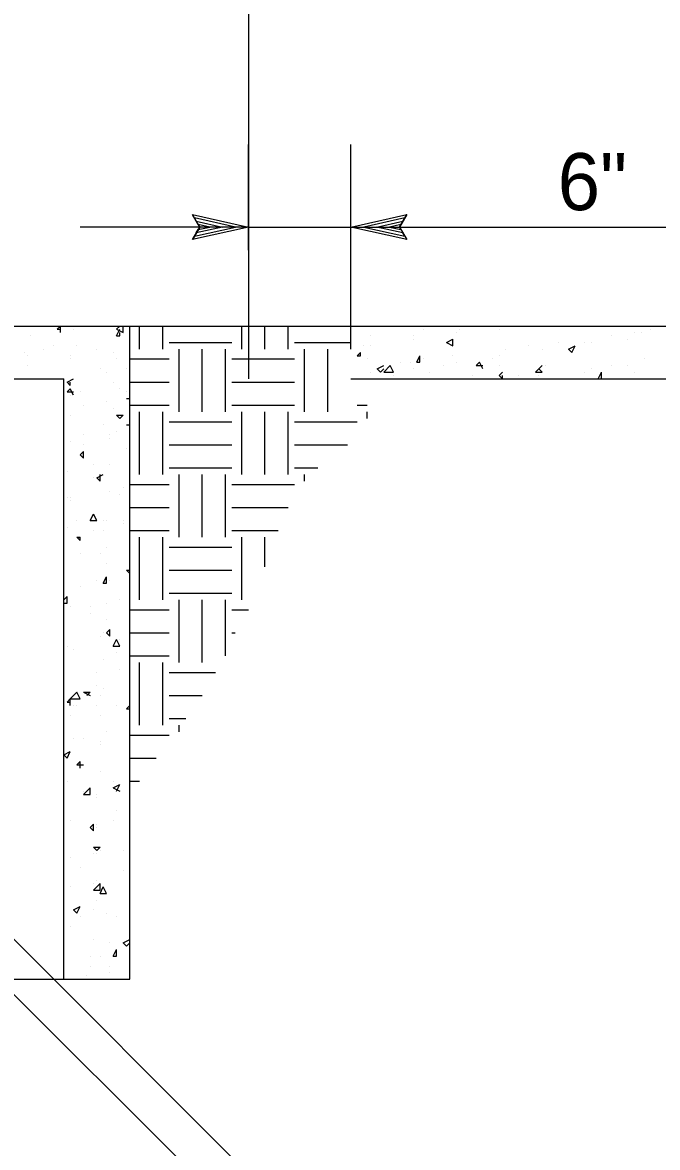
# Model space of a CAD drawing. Extents: x -119017 to -116080, y -104449 to -102845.
# Drawn here: x -116465.6 to -116398.8, y -103374.5 to -103256.1 of the extents above; entities that cross this region are included whole.
import ezdxf

# ---------------------------------------------------------------- set-up
doc = ezdxf.new("R2010")
doc.units = 0
for name, color, linetype in [('G-MARK', 7, 'Continuous'), ('G-TEXT', 7, 'Continuous'), ('Misc CnstDet(22)', 7, 'Continuous')]:
    doc.layers.add(name, color=color, linetype=linetype)

msp = doc.modelspace()

# ---------------------------------------------------------------- linework, layer by layer
at = {"layer": 'G-MARK'}
for p, q in [((-116441.82, -103280.07), (-116441.82, -103268.96)), ((-116431.07, -103290.48), (-116431.07, -103268.96)), ((-116441.82, -103277.64), (-116459.53, -103277.64)), ((-116441.82, -103277.64), (-116431.07, -103277.64)), ((-116431.07, -103277.64), (-116392.89, -103277.64))]:
    msp.add_line(p, q, dxfattribs=at)
at = {"layer": 'G-TEXT'}
for points in [[(-116447.73, -103276.32), (-116441.82, -103277.64), (-116447.73, -103278.95), (-116447.52, -103278.6), (-116443.19, -103277.64), (-116447.52, -103276.67), (-116447.31, -103277.02), (-116444.54, -103277.64), (-116447.31, -103278.25), (-116447.1, -103277.9), (-116445.9, -103277.64), (-116447.1, -103277.37), (-116446.94, -103277.64), (-116447.73, -103278.95), (-116446.94, -103277.64)], [(-116425.16, -103278.96), (-116431.07, -103277.64), (-116425.16, -103276.33), (-116425.37, -103276.68), (-116429.7, -103277.64), (-116425.37, -103278.61), (-116425.58, -103278.26), (-116428.35, -103277.64), (-116425.58, -103277.03), (-116425.79, -103277.38), (-116426.99, -103277.64), (-116425.79, -103277.91), (-116425.95, -103277.64), (-116425.16, -103276.33), (-116425.95, -103277.64)]]:
    msp.add_lwpolyline(points, close=True, dxfattribs=at)
at = {"layer": 'Misc CnstDet(22)'}
for p, q in [((-116441.82, -103024.96), (-116441.82, -103293.61)), ((-116431.07, -103277.64), (-116431.07, -103277.64)), ((-116441.82, -103283.19), (-116441.82, -103283.19)), ((-116614.33, -103288.05), (-116319.3, -103288.05)), ((-116462.3, -103288.05), (-116462.3, -103288.05)), ((-116461.96, -103288.4), (-116461.61, -103288.05)), ((-116461.96, -103288.4), (-116461.61, -103288.4)), ((-116461.61, -103288.75), (-116461.61, -103288.05)), ((-116460.22, -103288.4), (-116460.22, -103288.4)), ((-116455.71, -103288.4), (-116455.36, -103288.05)), ((-116455.71, -103288.4), (-116455.01, -103288.75)), ((-116455.71, -103289.09), (-116455.36, -103288.4)), ((-116455.36, -103289.09), (-116455.36, -103288.75)), ((-116455.01, -103288.75), (-116455.01, -103288.05)), ((-116454.32, -103356.78), (-116454.32, -103288.05)), ((-116453.28, -103290.48), (-116453.28, -103288.05)), ((-116450.85, -103290.48), (-116450.85, -103288.05)), ((-116442.52, -103290.48), (-116442.52, -103288.05)), ((-116440.09, -103290.48), (-116440.09, -103288.05)), ((-116437.66, -103290.48), (-116437.66, -103288.05)), ((-116423.43, -103288.4), (-116423.43, -103288.4)), ((-116421.35, -103288.05), (-116421.35, -103288.05)), ((-116419.96, -103288.75), (-116419.96, -103288.75)), ((-116419.61, -103288.4), (-116419.61, -103288.4)), ((-116415.45, -103288.4), (-116415.45, -103288.4)), ((-116401.22, -103288.75), (-116401.22, -103288.75)), ((-116400.52, -103288.75), (-116400.52, -103288.75)), ((-116399.48, -103288.4), (-116399.48, -103288.4)), ((-116464.73, -103289.09), (-116464.73, -103289.09)), ((-116455.71, -103289.09), (-116455.36, -103289.09)), ((-116450.16, -103289.79), (-116443.56, -103289.79)), ((-116436.97, -103289.79), (-116431.07, -103289.79)), ((-116428.98, -103289.09), (-116428.98, -103289.09)), ((-116424.47, -103289.09), (-116424.47, -103289.09)), ((-116424.47, -103289.44), (-116424.47, -103289.44)), ((-116421, -103289.79), (-116420.31, -103289.44)), ((-116421, -103289.79), (-116420.31, -103290.13)), ((-116420.31, -103290.13), (-116420.31, -103289.44)), ((-116409.2, -103289.79), (-116409.2, -103289.79)), ((-116406.42, -103289.79), (-116406.42, -103289.79)), ((-116405.73, -103289.79), (-116405.73, -103289.79)), ((-116403.64, -103289.09), (-116403.64, -103289.09)), ((-116401.91, -103289.44), (-116401.91, -103289.44)), ((-116465.43, -103290.83), (-116465.43, -103290.83)), ((-116463.34, -103290.48), (-116463.34, -103290.48)), ((-116462.3, -103290.13), (-116462.3, -103290.13)), ((-116459.87, -103290.13), (-116459.87, -103290.13)), ((-116457.79, -103290.48), (-116457.79, -103290.48)), ((-116456.06, -103290.83), (-116456.06, -103290.83)), ((-116449.11, -103297.08), (-116449.11, -103290.48)), ((-116446.68, -103297.08), (-116446.68, -103290.48)), ((-116444.25, -103297.08), (-116444.25, -103290.48)), ((-116435.92, -103297.08), (-116435.92, -103290.48)), ((-116433.49, -103297.08), (-116433.49, -103290.48)), ((-116430.37, -103291.18), (-116430.02, -103290.83)), ((-116430.02, -103291.18), (-116430.02, -103290.83)), ((-116429.68, -103290.13), (-116429.68, -103290.13)), ((-116428.98, -103290.13), (-116428.98, -103290.13)), ((-116414.75, -103290.48), (-116414.75, -103290.48)), ((-116412.32, -103290.13), (-116412.32, -103290.13)), ((-116410.93, -103290.48), (-116410.93, -103290.48)), ((-116410.93, -103290.48), (-116410.93, -103290.48)), ((-116408.16, -103290.48), (-116407.46, -103290.13)), ((-116408.16, -103290.48), (-116407.81, -103290.83)), ((-116407.81, -103290.83), (-116407.46, -103290.13)), ((-116465.08, -103291.18), (-116465.08, -103291.18)), ((-116465.08, -103292.22), (-116465.08, -103292.22)), ((-116460.57, -103291.18), (-116460.57, -103291.18)), ((-116460.57, -103291.52), (-116460.57, -103291.52)), ((-116455.71, -103291.52), (-116455.71, -103291.52)), ((-116454.32, -103291.52), (-116450.16, -103291.52)), ((-116443.56, -103291.52), (-116436.97, -103291.52)), ((-116430.37, -103291.18), (-116430.02, -103291.18)), ((-116429.33, -103291.52), (-116429.33, -103291.52)), ((-116428.29, -103292.56), (-116427.59, -103292.22)), ((-116427.59, -103292.91), (-116426.9, -103292.22)), ((-116426.55, -103292.91), (-116426.9, -103292.22)), ((-116425.86, -103291.87), (-116425.86, -103291.87)), ((-116424.82, -103291.87), (-116424.82, -103291.87)), ((-116424.12, -103291.87), (-116423.78, -103291.18)), ((-116424.12, -103291.87), (-116423.78, -103291.87)), ((-116423.78, -103291.87), (-116423.78, -103291.18)), ((-116423.43, -103291.52), (-116423.43, -103291.52)), ((-116421.35, -103292.22), (-116421.35, -103292.22)), ((-116420.31, -103291.18), (-116420.31, -103291.18)), ((-116419.96, -103291.87), (-116419.96, -103291.87)), ((-116419.96, -103291.87), (-116419.96, -103291.87)), ((-116417.88, -103292.22), (-116417.53, -103291.87)), ((-116417.88, -103292.22), (-116417.18, -103292.22)), ((-116417.18, -103292.56), (-116417.53, -103291.87)), ((-116416.14, -103291.52), (-116416.14, -103291.52)), ((-116415.45, -103291.18), (-116415.45, -103291.18)), ((-116415.45, -103292.22), (-116415.45, -103292.22)), ((-116411.63, -103292.91), (-116410.93, -103292.22)), ((-116410.59, -103292.22), (-116410.59, -103292.22)), ((-116403.64, -103292.22), (-116403.64, -103292.22)), ((-116401.91, -103292.22), (-116401.91, -103292.22)), ((-116400.17, -103291.52), (-116400.17, -103291.52)), ((-116457.44, -103292.56), (-116457.44, -103292.56)), ((-116456.75, -103292.91), (-116456.75, -103292.91)), ((-116454.67, -103292.56), (-116454.67, -103292.56)), ((-116428.98, -103292.91), (-116428.98, -103292.91)), ((-116428.29, -103292.56), (-116427.94, -103292.91)), ((-116427.94, -103292.91), (-116427.59, -103292.56)), ((-116427.59, -103292.56), (-116427.59, -103292.56)), ((-116427.59, -103292.91), (-116426.55, -103292.91)), ((-116426.55, -103293.26), (-116426.55, -103293.26)), ((-116424.47, -103292.56), (-116424.47, -103292.56)), ((-116422.73, -103292.91), (-116422.73, -103292.91)), ((-116418.22, -103293.26), (-116418.22, -103293.26)), ((-116415.45, -103293.26), (-116415.1, -103292.91)), ((-116415.45, -103293.26), (-116415.1, -103293.61)), ((-116415.1, -103293.61), (-116415.1, -103293.26)), ((-116413.36, -103293.26), (-116413.36, -103293.26)), ((-116411.63, -103292.91), (-116410.93, -103292.91)), ((-116410.93, -103292.91), (-116411.28, -103292.56)), ((-116411.28, -103293.26), (-116411.28, -103293.26)), ((-116406.42, -103292.91), (-116406.42, -103292.91)), ((-116405.73, -103292.56), (-116405.73, -103292.56)), ((-116405.73, -103292.56), (-116405.73, -103292.56)), ((-116405.03, -103293.61), (-116404.69, -103292.91)), ((-116404.69, -103293.61), (-116404.69, -103292.91)), ((-116401.22, -103292.91), (-116401.22, -103292.91)), ((-116468.2, -103293.61), (-116461.26, -103293.61)), ((-116462.65, -103293.61), (-116462.65, -103293.61)), ((-116462.3, -103293.61), (-116462.3, -103293.61)), ((-116461.26, -103356.78), (-116461.26, -103293.61)), ((-116460.91, -103293.95), (-116460.22, -103293.61)), ((-116460.91, -103293.95), (-116460.57, -103294.3)), ((-116460.91, -103294.99), (-116460.57, -103294.65)), ((-116460.57, -103294.3), (-116460.57, -103293.95)), ((-116460.57, -103294.3), (-116460.57, -103294.3)), ((-116460.22, -103295.34), (-116460.57, -103294.65)), ((-116456.06, -103293.95), (-116456.06, -103293.95)), ((-116455.36, -103294.65), (-116455.36, -103294.65)), ((-116454.32, -103293.95), (-116450.16, -103293.95)), ((-116443.56, -103293.95), (-116436.97, -103293.95)), ((-116431.07, -103293.61), (-116337.35, -103293.61)), ((-116431.07, -103293.61), (-116431.07, -103293.61)), ((-116414.75, -103293.61), (-116414.75, -103293.61)), ((-116410.93, -103293.61), (-116410.93, -103293.61)), ((-116408.85, -103293.61), (-116408.85, -103293.61)), ((-116405.03, -103293.61), (-116404.69, -103293.61)), ((-116460.91, -103294.99), (-116460.22, -103294.99)), ((-116460.57, -103295.34), (-116460.57, -103295.34)), ((-116459.53, -103294.99), (-116459.53, -103294.99)), ((-116454.67, -103294.99), (-116454.67, -103294.99)), ((-116454.67, -103295.69), (-116454.32, -103295.69)), ((-116454.67, -103295.69), (-116454.32, -103295.69)), ((-116459.18, -103296.38), (-116459.18, -103296.38)), ((-116456.75, -103296.03), (-116456.75, -103296.03)), ((-116456.06, -103296.73), (-116456.06, -103296.73)), ((-116454.32, -103296.38), (-116450.16, -103296.38)), ((-116443.56, -103296.38), (-116436.97, -103296.38)), ((-116430.37, -103296.38), (-116429.33, -103296.38)), ((-116460.57, -103297.42), (-116460.57, -103297.42)), ((-116455.71, -103297.42), (-116455.36, -103297.77)), ((-116455.71, -103297.42), (-116455.01, -103297.42)), ((-116455.36, -103297.77), (-116455.01, -103297.42)), ((-116453.28, -103303.67), (-116453.28, -103297.08)), ((-116450.85, -103303.67), (-116450.85, -103297.08)), ((-116450.16, -103298.12), (-116443.56, -103298.12)), ((-116442.52, -103303.67), (-116442.52, -103297.08)), ((-116440.09, -103303.67), (-116440.09, -103297.08)), ((-116437.66, -103303.67), (-116437.66, -103297.08)), ((-116436.97, -103298.12), (-116430.37, -103298.12)), ((-116429.33, -103297.77), (-116429.33, -103297.08)), ((-116457.1, -103298.46), (-116457.1, -103298.46)), ((-116455.71, -103299.16), (-116455.71, -103299.16)), ((-116454.67, -103298.46), (-116454.32, -103298.46)), ((-116454.67, -103298.46), (-116454.32, -103298.46)), ((-116461.26, -103299.51), (-116461.26, -103299.51)), ((-116460.57, -103300.2), (-116460.57, -103300.2)), ((-116459.18, -103299.51), (-116459.18, -103299.51)), ((-116459.18, -103300.55), (-116459.18, -103300.55)), ((-116456.4, -103299.51), (-116456.4, -103299.51)), ((-116456.4, -103299.85), (-116456.4, -103299.85)), ((-116450.16, -103300.55), (-116443.56, -103300.55)), ((-116436.97, -103300.55), (-116431.41, -103300.55)), ((-116459.53, -103301.59), (-116459.18, -103301.24)), ((-116459.53, -103301.59), (-116459.18, -103301.94)), ((-116459.18, -103301.94), (-116459.18, -103301.24)), ((-116454.67, -103300.89), (-116454.67, -103300.89)), ((-116458.14, -103302.63), (-116458.14, -103302.63)), ((-116456.4, -103302.63), (-116456.4, -103302.63)), ((-116460.91, -103303.32), (-116460.91, -103303.32)), ((-116458.14, -103304.02), (-116458.14, -103304.02)), ((-116457.79, -103304.02), (-116457.1, -103303.67)), ((-116457.79, -103304.02), (-116457.44, -103304.37)), ((-116457.44, -103303.67), (-116457.44, -103303.67)), ((-116457.44, -103304.37), (-116457.44, -103303.67)), ((-116450.16, -103302.98), (-116443.56, -103302.98)), ((-116449.11, -103310.27), (-116449.11, -103303.67)), ((-116446.68, -103310.27), (-116446.68, -103303.67)), ((-116444.25, -103310.27), (-116444.25, -103303.67)), ((-116436.97, -103302.98), (-116434.54, -103302.98)), ((-116435.92, -103304.37), (-116435.92, -103303.67)), ((-116455.01, -103305.06), (-116455.01, -103305.06)), ((-116454.32, -103304.71), (-116450.16, -103304.71)), ((-116443.56, -103304.71), (-116436.97, -103304.71)), ((-116460.91, -103306.1), (-116460.91, -103306.1)), ((-116460.57, -103306.1), (-116460.57, -103306.1)), ((-116460.57, -103306.45), (-116460.57, -103306.45)), ((-116456.4, -103305.41), (-116456.4, -103305.41)), ((-116455.36, -103305.75), (-116455.36, -103305.75)), ((-116454.32, -103307.14), (-116450.16, -103307.14)), ((-116443.56, -103307.14), (-116437.66, -103307.14)), ((-116459.87, -103308.53), (-116459.87, -103308.53)), ((-116458.49, -103308.53), (-116458.14, -103307.84)), ((-116458.49, -103308.53), (-116457.79, -103308.53)), ((-116457.79, -103308.53), (-116458.14, -103307.84)), ((-116457.1, -103308.53), (-116457.1, -103308.53)), ((-116456.75, -103308.53), (-116456.75, -103308.53)), ((-116455.01, -103308.53), (-116455.01, -103308.53)), ((-116455.01, -103308.88), (-116455.01, -103308.88)), ((-116460.91, -103309.22), (-116460.91, -103309.22)), ((-116458.14, -103309.57), (-116458.14, -103309.57)), ((-116457.1, -103309.57), (-116457.1, -103309.57)), ((-116454.32, -103309.57), (-116450.16, -103309.57)), ((-116443.56, -103309.57), (-116438.7, -103309.57)), ((-116459.87, -103310.27), (-116459.53, -103310.61)), ((-116459.87, -103310.27), (-116459.53, -103310.27)), ((-116459.53, -103310.61), (-116459.53, -103310.27)), ((-116453.28, -103316.86), (-116453.28, -103310.27)), ((-116450.85, -103316.86), (-116450.85, -103310.27)), ((-116442.52, -103316.86), (-116442.52, -103310.27)), ((-116440.09, -103313.39), (-116440.09, -103310.27)), ((-116461.26, -103312), (-116461.26, -103312)), ((-116459.53, -103312), (-116459.53, -103312)), ((-116457.44, -103312), (-116457.44, -103312)), ((-116456.75, -103311.31), (-116456.75, -103311.31)), ((-116450.16, -103311.31), (-116443.56, -103311.31)), ((-116456.75, -103313.04), (-116456.75, -103313.04)), ((-116461.26, -103314.78), (-116461.26, -103314.78)), ((-116457.79, -103314.78), (-116457.79, -103314.78)), ((-116457.1, -103315.12), (-116456.75, -103314.43)), ((-116456.75, -103314.43), (-116456.75, -103314.43)), ((-116456.75, -103315.12), (-116456.75, -103314.43)), ((-116456.4, -103314.78), (-116456.4, -103314.78)), ((-116454.67, -103313.74), (-116454.32, -103314.08)), ((-116454.67, -103313.74), (-116454.32, -103313.74)), ((-116450.16, -103313.74), (-116443.56, -103313.74)), ((-116459.53, -103315.47), (-116459.53, -103315.47)), ((-116457.1, -103315.12), (-116456.75, -103315.12)), ((-116461.26, -103316.86), (-116460.91, -103316.51)), ((-116460.91, -103317.21), (-116460.91, -103316.51)), ((-116455.36, -103316.86), (-116455.36, -103316.86)), ((-116450.16, -103316.17), (-116443.56, -103316.17)), ((-116449.11, -103323.46), (-116449.11, -103316.86)), ((-116446.68, -103323.46), (-116446.68, -103316.86)), ((-116444.25, -103322.76), (-116444.25, -103316.86)), ((-116461.26, -103317.21), (-116460.91, -103317.21)), ((-116460.57, -103317.55), (-116460.57, -103317.55)), ((-116458.49, -103317.55), (-116458.49, -103317.55)), ((-116458.49, -103318.25), (-116458.49, -103318.25)), ((-116456.75, -103317.21), (-116456.75, -103317.21)), ((-116454.32, -103317.9), (-116450.16, -103317.9)), ((-116443.56, -103317.9), (-116441.82, -103317.9)), ((-116456.75, -103318.94), (-116456.75, -103318.94)), ((-116457.44, -103320.68), (-116457.44, -103320.68)), ((-116457.1, -103320.33), (-116457.1, -103320.33)), ((-116456.75, -103320.33), (-116456.4, -103319.98)), ((-116456.75, -103320.33), (-116456.4, -103320.68)), ((-116456.4, -103320.68), (-116456.4, -103319.98)), ((-116454.32, -103320.33), (-116450.16, -103320.33)), ((-116443.56, -103320.33), (-116443.21, -103320.33)), ((-116460.91, -103321.72), (-116460.91, -103321.72)), ((-116456.06, -103321.72), (-116455.71, -103321.03)), ((-116456.06, -103321.72), (-116455.36, -103321.72)), ((-116455.36, -103321.72), (-116455.71, -103321.03)), ((-116455.36, -103321.03), (-116455.36, -103321.03)), ((-116460.22, -103322.07), (-116460.22, -103322.07)), ((-116455.71, -103322.41), (-116455.71, -103322.41)), ((-116454.32, -103322.76), (-116450.16, -103322.76)), ((-116457.1, -103323.11), (-116457.1, -103323.11)), ((-116455.36, -103324.15), (-116455.36, -103324.15)), ((-116453.28, -103330.05), (-116453.28, -103323.46)), ((-116450.85, -103330.05), (-116450.85, -103323.46)), ((-116457.79, -103324.5), (-116457.79, -103324.5)), ((-116450.16, -103324.5), (-116445.3, -103324.5)), ((-116460.57, -103327.27), (-116459.87, -103326.58)), ((-116459.53, -103327.27), (-116459.87, -103326.58)), ((-116459.18, -103326.58), (-116458.49, -103326.93)), ((-116459.18, -103326.58), (-116458.49, -103326.58)), ((-116458.83, -103326.93), (-116458.49, -103326.58)), ((-116457.79, -103325.88), (-116457.79, -103325.88)), ((-116457.1, -103326.23), (-116457.1, -103326.23)), ((-116460.91, -103327.62), (-116460.57, -103327.27)), ((-116460.91, -103327.62), (-116460.57, -103327.62)), ((-116460.57, -103327.27), (-116459.53, -103327.27)), ((-116460.57, -103327.97), (-116460.57, -103327.27)), ((-116457.44, -103326.93), (-116457.44, -103326.93)), ((-116454.32, -103327.27), (-116454.32, -103327.27)), ((-116450.16, -103326.93), (-116446.68, -103326.93)), ((-116460.57, -103329.01), (-116460.57, -103329.01)), ((-116460.22, -103327.97), (-116460.22, -103327.97)), ((-116459.87, -103327.97), (-116459.87, -103327.97)), ((-116457.79, -103327.97), (-116457.79, -103327.97)), ((-116457.44, -103329.01), (-116457.44, -103329.01)), ((-116455.71, -103327.97), (-116455.71, -103327.97)), ((-116455.71, -103327.97), (-116455.71, -103327.97)), ((-116454.67, -103328.31), (-116454.32, -103327.97)), ((-116454.67, -103328.31), (-116454.32, -103328.31)), ((-116450.16, -103329.36), (-116448.42, -103329.36)), ((-116449.11, -103330.74), (-116449.11, -103330.05)), ((-116456.75, -103330.74), (-116456.75, -103330.74)), ((-116454.32, -103331.09), (-116450.16, -103331.09)), ((-116460.22, -103331.44), (-116460.22, -103331.44)), ((-116459.18, -103331.44), (-116459.18, -103331.44)), ((-116457.44, -103331.79), (-116457.44, -103331.79)), ((-116457.44, -103332.13), (-116457.44, -103332.13)), ((-116461.26, -103333.17), (-116460.57, -103332.83)), ((-116461.26, -103333.17), (-116460.91, -103333.52)), ((-116460.91, -103333.52), (-116460.57, -103332.83)), ((-116454.32, -103333.52), (-116451.54, -103333.52)), ((-116459.87, -103334.21), (-116459.53, -103333.87)), ((-116459.87, -103334.21), (-116459.18, -103334.21)), ((-116459.53, -103334.56), (-116459.53, -103333.87)), ((-116459.18, -103334.21), (-116459.18, -103334.21)), ((-116457.44, -103334.91), (-116457.44, -103334.91)), ((-116399.13, -103419.95), (-116483.48, -103335.6)), ((-116460.91, -103335.95), (-116460.91, -103335.95)), ((-116456.06, -103335.95), (-116456.06, -103335.95)), ((-116454.32, -103335.95), (-116453.28, -103335.95)), ((-116459.18, -103337.34), (-116458.49, -103336.64)), ((-116459.18, -103336.99), (-116459.18, -103336.99)), ((-116458.49, -103337.34), (-116458.49, -103336.64)), ((-116456.06, -103336.64), (-116455.36, -103336.3)), ((-116456.06, -103336.64), (-116455.36, -103336.99)), ((-116455.71, -103336.99), (-116455.36, -103336.3)), ((-116455.71, -103336.99), (-116455.71, -103336.99)), ((-116381.78, -103442.85), (-116487.29, -103337.69)), ((-116459.18, -103337.34), (-116458.49, -103337.34)), ((-116457.79, -103337.34), (-116457.79, -103337.34)), ((-116457.79, -103337.69), (-116457.79, -103337.69)), ((-116455.71, -103339.07), (-116455.71, -103339.07)), ((-116460.57, -103340.12), (-116460.57, -103340.12)), ((-116458.49, -103340.81), (-116458.14, -103340.46)), ((-116458.49, -103340.81), (-116458.14, -103341.16)), ((-116458.14, -103340.46), (-116458.14, -103340.46)), ((-116458.14, -103341.16), (-116458.14, -103340.46)), ((-116457.79, -103340.46), (-116457.79, -103340.46)), ((-116457.79, -103340.81), (-116457.79, -103340.81)), ((-116456.06, -103340.12), (-116456.06, -103340.12)), ((-116458.14, -103342.89), (-116457.79, -103343.24)), ((-116458.14, -103342.89), (-116457.44, -103342.89)), ((-116457.79, -103343.24), (-116457.44, -103342.89)), ((-116460.57, -103343.93), (-116460.57, -103343.93)), ((-116458.14, -103343.59), (-116458.14, -103343.59)), ((-116457.79, -103343.59), (-116457.79, -103343.59)), ((-116457.44, -103343.24), (-116457.44, -103343.24)), ((-116455.01, -103343.24), (-116455.01, -103343.24)), ((-116459.53, -103344.97), (-116459.53, -103344.97)), ((-116455.01, -103345.32), (-116455.01, -103345.32)), ((-116458.14, -103346.71), (-116458.14, -103346.71)), ((-116458.14, -103347.4), (-116457.44, -103346.71)), ((-116457.79, -103346.36), (-116457.79, -103346.36)), ((-116457.44, -103346.71), (-116457.44, -103346.71)), ((-116457.44, -103347.4), (-116457.44, -103346.71)), ((-116460.57, -103347.06), (-116460.57, -103347.06)), ((-116458.14, -103347.4), (-116457.44, -103347.4)), ((-116457.44, -103347.75), (-116457.1, -103347.06)), ((-116457.44, -103347.75), (-116456.75, -103347.75)), ((-116456.75, -103347.75), (-116457.1, -103347.06)), ((-116457.79, -103348.45), (-116457.79, -103348.45)), ((-116460.22, -103349.49), (-116459.53, -103349.14)), ((-116460.22, -103349.49), (-116459.87, -103349.83)), ((-116459.87, -103349.83), (-116459.53, -103349.14)), ((-116459.53, -103350.18), (-116459.53, -103350.18)), ((-116458.14, -103349.49), (-116458.14, -103349.49)), ((-116456.75, -103349.83), (-116456.75, -103349.83)), ((-116455.71, -103350.18), (-116455.71, -103350.18)), ((-116460.57, -103351.22), (-116460.57, -103351.22)), ((-116458.14, -103352.61), (-116458.14, -103352.61)), ((-116455.01, -103352.96), (-116454.32, -103352.61)), ((-116456.4, -103352.96), (-116456.4, -103352.96)), ((-116456.06, -103354.35), (-116455.71, -103353.65)), ((-116455.71, -103354.35), (-116455.71, -103353.65)), ((-116455.01, -103352.96), (-116454.67, -103353.3)), ((-116454.67, -103353.3), (-116454.32, -103352.96)), ((-116458.49, -103354.35), (-116458.49, -103354.35)), ((-116457.44, -103354.35), (-116457.44, -103354.35)), ((-116456.06, -103354.35), (-116455.71, -103354.35)), ((-116461.26, -103355.39), (-116461.26, -103355.39)), ((-116458.49, -103355.39), (-116458.49, -103355.39)), ((-116456.4, -103355.39), (-116456.4, -103355.39)), ((-116456.4, -103356.08), (-116456.4, -103356.08)), ((-116571.64, -103356.78), (-116454.32, -103356.78)), ((-116458.83, -103356.43), (-116458.83, -103356.43)), ((-116456.4, -103356.78), (-116456.4, -103356.78)), ((-116456.4, -103356.78), (-116456.06, -103356.78))]:
    msp.add_line(p, q, dxfattribs=at)

# ---------------------------------------------------------------- texts
msp.add_text('6"', height=6, dxfattribs=at).set_placement((-116409.29, -103275.86))

doc.saveas('drawing.dxf')
